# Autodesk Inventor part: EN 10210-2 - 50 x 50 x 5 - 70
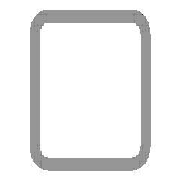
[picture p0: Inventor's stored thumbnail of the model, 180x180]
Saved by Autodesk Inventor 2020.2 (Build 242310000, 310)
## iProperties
IsCustomPart: 1
_CCFamilyMember: 16
_CCFamilyDisplayName: DIN EN 10210-2 (USAS B17.1 quadratisch) - Rohrleitung — In Klammern angegebene Größen wurden aufgehoben
_FrameMemberDoc: Frame Member File
_Version: 15.0.0
_GetPNFromCC: 1
Created: 2019-10
Part Number: EN 10210-2 - 50 x 50 x 5 - 70
Material: Stahl, weich
Description: Rohrleitung
Document SubType Name: Modeling
Standard: DIN
Designer: lutzd
Standard Revision: 2006-07
Standards Organization: DIN
Language: de-DE
Size Designation: 50 x 50 x 5
Categories: <MemberInstance><Categories><Category DisplayName="Profile" InternalName="089c4875-fa83-4c05-b084-43b9cc11f5ed" Mnemonic="GRDR"><CategoryParameter DisplayName="
Stock Number: 50 x 50 x 5
Mass: 479.81 g
Surface Area: 254.441 cm^2
Volume: 61.1222 cm^3
Density: 7.85 g/cm^3
Appearance: Semi-Polished(8)
G_L: 70,000 mm
G_W: 50,000 mm
G_H: 50,000 mm
Dimensions: 50x50x70 mm
Mass: 0,48 kg
DocNumber: ADSK-014288
Folder: .
+70311937-DACF-4986-9D2D-EF8181D38695+SCHNITTDETAIL1: Schnittwinkel 90,00 grd
VLT_Material: Stahl, weich
Title: Profil-Bauteil
Author: lutzd
Revision Number: -
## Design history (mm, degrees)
node "Startebene"
node "Endebene"
sketch "Skizze"
  geometry: L1 (-25, -17.5)-(-25, 17.5); L2 (-17.5, 25)-(17.5, 25); L3 (25, 17.5)-(25, -17.5); L4 (17.5, -25)-(-17.5, -25); L5 (-15, 20)-(15, 20); L6 (20, 15)-(20, -15); L7 (15, -20)-(-15, -20); L8 (-20, -15)-(-20, 15); L9 (0, 37.175)-(0, -37.175) reference; L10 (-37.175, 0)-(37.175, 0) reference; A1 r 7.5 centre (-17.5, -17.5) between (-25, -17.5) and (-17.5, -25); A2 r 7.5 centre (-17.5, 17.5) between (-17.5, 25) and (-25, 17.5); A3 r 7.5 centre (17.5, 17.5) between (25, 17.5) and (17.5, 25); A4 r 7.5 centre (17.5, -17.5) between (17.5, -25) and (25, -17.5); A5 r 5 centre (-15, -15) between (-20, -15) and (-15, -20); A6 r 5 centre (-15, 15) between (-15, 20) and (-20, 15); A7 r 5 centre (15, 15) between (20, 15) and (15, 20); A8 r 5 centre (15, -15) between (15, -20) and (20, -15)
  constraints: 16 end point, 16 point on circle, 16 tangent, 8 centre point, 6 equal radius, 4 parallel, 2 perpendicular, 2 other
  dimensions: "d7" = 7.5 radius of A1 (= G_IR); "d10" = 50 distance between parallel lines of L2 L4 (= G_H); "d11" = 50 distance between parallel lines of L1 L3 (= G_W); "d12" = 5 distance between parallel lines of L3 L6 (= G_T); "d15" = 25 distance between parallel lines of L2 L10 (= 0.5 x d10); "d16" = 25 distance between parallel lines of L9 L3 (= 0.5 x d11); "d19" = 5 radius of A5 (= G_T); "d20" = 5 distance between parallel lines of L4 L7 (= G_T)
extrude "Körper" new body sketch "Skizze" stored distance "d3" = 70 (= G_L); taper "d4" = 0 deg
node "Driven Length"
  sketch "Sketch3"
    geometry: L1 (0, 0)-(10, 0) reference
    constraints: 2 end point, 1 horizontal
  workplane "Work Plane3"
  sketch "Sketch4"
    geometry: L1 (-2, 25)-(12, 25) reference; L2 (-2, 95)-(12, 95) reference
    dimensions: "d18" = 70 distance between parallel lines of L1 L2 (derived)
workplane "Arbeitsebene4"
feature "Trennen1"
body "Solid1"
other parameters: "G_W" = 50 [user parameter; used in 1 equation term], "G_H" = 50 [user parameter; used in 1 equation term], "G_T" = 5 [user parameter; used in 3 equation terms], "G_IR" = 7.5 [user parameter; used in 1 equation term], "G_L" = 70 (= d18) [user parameter; used in 1 equation term], "G_OFFSET_START" = -25 [user parameter; used in 1 equation term], "G_OFFSET_END" = 0 [user parameter; used in 1 equation term], "d13" = 25 (= -G_OFFSET_START), "d14" = 95 (= G_OFFSET_END + B_L), "B_L" = 95 [user parameter; used in 1 equation term], "d17" = 90 deg
